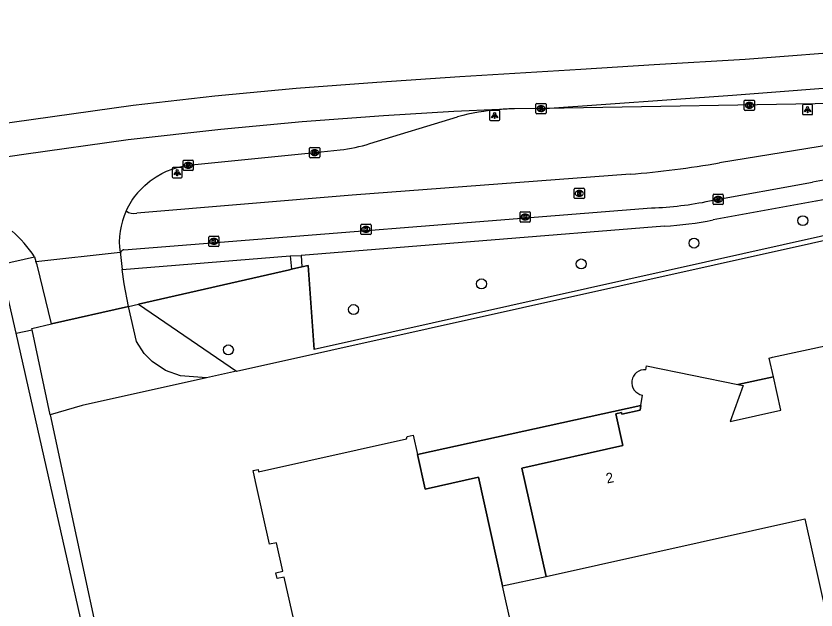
# Model space of a CAD drawing. Extents: x 160806 to 161707, y 383697 to 384148.
# Drawn here: x 161561.9 to 161640.7, y 383938.2 to 383996.6 of the extents above; entities that cross this region are included whole.
import ezdxf

# ---------------------------------------------------------------- set-up
doc = ezdxf.new("R2010")
doc.units = 0
for name, color, linetype in [('IMGEO_Boom', 7, 'Continuous'), ('IMGEO_Fietspad_gesloten', 7, 'Continuous'), ('IMGEO_Groenvoorziening', 7, 'Continuous'), ('IMGEO_Hek', 7, 'Continuous'), ('IMGEO_Kolk', 7, 'Continuous'), ('IMGEO_Lichtpunt', 7, 'Continuous'), ('IMGEO_Pand', 7, 'Continuous'), ('IMGEO_Pand_nummerreeks', 7, 'Continuous'), ('IMGEO_Pand_overbouw', 7, 'Continuous'), ('IMGEO_Rijbaan_lokaal_gesloten', 7, 'Continuous'), ('IMGEO_Rijbaan_lokaal_open', 7, 'Continuous'), ('IMGEO_Rioolput', 7, 'Continuous'), ('IMGEO_Voetpad_open', 7, 'Continuous')]:
    doc.layers.add(name, color=color, linetype=linetype)

msp = doc.modelspace()

# ---------------------------------------------------------------- linework, layer by layer
at = {"layer": 'IMGEO_Boom'}
for centre in [(161639.398, 383976.482), (161628.685, 383974.273), (161617.583, 383972.225), (161607.767, 383970.262), (161595.169, 383967.742), (161582.85, 383963.771)]:
    msp.add_circle(centre, 0.489, dxfattribs=at)
at = {"layer": 'IMGEO_Fietspad_gesloten'}
for points in [[(161652.014, 383985.545), (161631.18, 383982.155)], [(161622.388, 383981.04), (161595.026, 383978.975), (161573.832, 383977.231)], [(161630.223, 383978.423), (161640.346, 383980.265)], [(161572.575, 383973.622), (161624.515, 383977.73)], [(161572.194, 383973.368), (161572.229, 383973.164)]]:
    msp.add_lwpolyline(points, dxfattribs=at)
for centre, radius, start, end in [((161612.123, 384097.202), 116.615, 275.04997, 279.40535), ((161690.597, 383714.53), 270.445, 98.22915, 100.70838), ((161623.202, 384012.399), 34.694, 272.16899, 281.67565), ((161573.512, 383978.353), 1.167, 232.06416, 285.89031), ((161572.621, 383973.228), 0.397, 96.6008, 189.26013)]:
    msp.add_arc(centre, radius, start, end, dxfattribs=at)
at = {"layer": 'IMGEO_Groenvoorziening'}
for points in [[(161661.841, 383973.012), (161660.383, 383979.219), (161591.289, 383963.808), (161590.712, 383972.073), (161590.074, 383971.928)], [(161589.067, 383971.699), (161588.861, 383971.653), (161574, 383968.274)], [(161573.018, 383968.051), (161574, 383968.274)], [(161574, 383968.274), (161583.645, 383961.688)]]:
    msp.add_lwpolyline(points, dxfattribs=at)
at = {"layer": 'IMGEO_Hek'}
for points in [[(161590.074, 383971.928), (161590.712, 383972.073), (161591.289, 383963.808)], [(161574, 383968.274), (161588.861, 383971.653)], [(161588.861, 383971.653), (161589.067, 383971.699)], [(161589.067, 383971.699), (161590.074, 383971.928)], [(161573.018, 383968.051), (161574, 383968.274)], [(161565.428, 383966.326), (161573.018, 383968.051)], [(161563.498, 383965.879), (161565.428, 383966.326)], [(161563.526, 383965.747), (161563.498, 383965.879)], [(161565.319, 383957.39), (161563.526, 383965.747)]]:
    msp.add_lwpolyline(points, dxfattribs=at)
at = {"layer": 'IMGEO_Kolk'}
for p, q in [((161613.127, 383987.079), (161613.127, 383987.931)), ((161613.202, 383988.005), (161614.054, 383988.005)), ((161613.615, 383987.785), (161613.64, 383987.785)), ((161614.128, 383987.931), (161614.128, 383987.079)), ((161633.638, 383987.404), (161633.638, 383988.256)), ((161633.713, 383988.33), (161634.565, 383988.33)), ((161634.126, 383988.11), (161634.151, 383988.11)), ((161634.639, 383988.256), (161634.639, 383987.404)), ((161614.054, 383987.005), (161613.202, 383987.005)), ((161613.638, 383987.225), (161613.613, 383987.225)), ((161634.565, 383987.33), (161633.713, 383987.33)), ((161634.149, 383987.55), (161634.124, 383987.55)), ((161590.847, 383982.749), (161590.847, 383983.601)), ((161590.922, 383983.675), (161591.774, 383983.675)), ((161591.335, 383983.455), (161591.36, 383983.455)), ((161591.848, 383983.601), (161591.848, 383982.749)), ((161578.396, 383981.499), (161578.396, 383982.351)), ((161578.471, 383982.425), (161579.323, 383982.425)), ((161579.397, 383982.351), (161579.397, 383981.499)), ((161591.774, 383982.675), (161590.922, 383982.675)), ((161591.358, 383982.895), (161591.333, 383982.895)), ((161578.907, 383981.645), (161578.882, 383981.645)), ((161578.884, 383982.205), (161578.909, 383982.205)), ((161579.323, 383981.425), (161578.471, 383981.425)), ((161630.56, 383978.15), (161630.56, 383979.002)), ((161630.635, 383979.076), (161631.487, 383979.076)), ((161631.048, 383978.856), (161631.073, 383978.856)), ((161631.561, 383979.002), (161631.561, 383978.15)), ((161631.487, 383978.076), (161630.635, 383978.076)), ((161631.071, 383978.296), (161631.046, 383978.296)), ((161611.562, 383976.422), (161611.562, 383977.274)), ((161611.637, 383977.348), (161612.489, 383977.348)), ((161612.05, 383977.128), (161612.075, 383977.128)), ((161612.563, 383977.274), (161612.563, 383976.422)), ((161595.889, 383975.2), (161595.889, 383976.052)), ((161595.964, 383976.126), (161596.816, 383976.126)), ((161596.89, 383976.052), (161596.89, 383975.2)), ((161612.489, 383976.348), (161611.637, 383976.348)), ((161612.073, 383976.568), (161612.048, 383976.568)), ((161596.4, 383975.346), (161596.375, 383975.346)), ((161596.377, 383975.906), (161596.402, 383975.906)), ((161580.923, 383974.019), (161580.923, 383974.871)), ((161580.998, 383974.945), (161581.85, 383974.945)), ((161581.411, 383974.725), (161581.436, 383974.725)), ((161581.924, 383974.871), (161581.924, 383974.019)), ((161596.816, 383975.126), (161595.964, 383975.126)), ((161581.85, 383973.945), (161580.998, 383973.945)), ((161581.434, 383974.165), (161581.409, 383974.165))]:
    msp.add_line(p, q, dxfattribs=at)
for points in [[(161613.127, 383987.079), (161613.127, 383987.931)], [(161613.202, 383988.005), (161614.054, 383988.005)], [(161614.128, 383987.931), (161614.128, 383987.079)], [(161633.638, 383987.404), (161633.638, 383988.256)], [(161633.713, 383988.33), (161634.565, 383988.33)], [(161633.959, 383988.03), (161634.082, 383988.03), (161634.082, 383987.879), (161634.212, 383988.03), (161634.376, 383988.03), (161634.23, 383987.879), (161634.383, 383987.63), (161634.231, 383987.63), (161634.146, 383987.794), (161634.082, 383987.727), (161634.082, 383987.63), (161633.959, 383987.63), (161633.959, 383988.03)], [(161634.639, 383988.256), (161634.639, 383987.404)], [(161614.054, 383987.005), (161613.202, 383987.005)], [(161613.448, 383987.705), (161613.571, 383987.705), (161613.571, 383987.554), (161613.701, 383987.705), (161613.865, 383987.705), (161613.719, 383987.554), (161613.872, 383987.305), (161613.72, 383987.305), (161613.635, 383987.469), (161613.571, 383987.402), (161613.571, 383987.305), (161613.448, 383987.305), (161613.448, 383987.705)], [(161634.565, 383987.33), (161633.713, 383987.33)], [(161590.847, 383982.749), (161590.847, 383983.601)], [(161590.922, 383983.675), (161591.774, 383983.675)], [(161591.168, 383983.375), (161591.291, 383983.375), (161591.291, 383983.224), (161591.421, 383983.375), (161591.585, 383983.375), (161591.439, 383983.224), (161591.592, 383982.975), (161591.44, 383982.975), (161591.355, 383983.139), (161591.291, 383983.072), (161591.291, 383982.975), (161591.168, 383982.975), (161591.168, 383983.375)], [(161591.848, 383983.601), (161591.848, 383982.749)], [(161578.396, 383981.499), (161578.396, 383982.351)], [(161578.471, 383982.425), (161579.323, 383982.425)], [(161579.397, 383982.351), (161579.397, 383981.499)], [(161591.774, 383982.675), (161590.922, 383982.675)], [(161578.717, 383982.125), (161578.84, 383982.125), (161578.84, 383981.974), (161578.97, 383982.125), (161579.134, 383982.125), (161578.988, 383981.974), (161579.141, 383981.725), (161578.989, 383981.725), (161578.904, 383981.889), (161578.84, 383981.822), (161578.84, 383981.725), (161578.717, 383981.725), (161578.717, 383982.125)], [(161579.323, 383981.425), (161578.471, 383981.425)], [(161630.56, 383978.15), (161630.56, 383979.002)], [(161630.635, 383979.076), (161631.487, 383979.076)], [(161630.881, 383978.776), (161631.004, 383978.776), (161631.004, 383978.625), (161631.134, 383978.776), (161631.298, 383978.776), (161631.152, 383978.625), (161631.305, 383978.376), (161631.153, 383978.376), (161631.068, 383978.54), (161631.004, 383978.473), (161631.004, 383978.376), (161630.881, 383978.376), (161630.881, 383978.776)], [(161631.561, 383979.002), (161631.561, 383978.15)], [(161631.487, 383978.076), (161630.635, 383978.076)], [(161611.562, 383976.422), (161611.562, 383977.274)], [(161611.637, 383977.348), (161612.489, 383977.348)], [(161611.883, 383977.048), (161612.006, 383977.048), (161612.006, 383976.897), (161612.136, 383977.048), (161612.3, 383977.048), (161612.154, 383976.897), (161612.307, 383976.648), (161612.155, 383976.648), (161612.07, 383976.812), (161612.006, 383976.745), (161612.006, 383976.648), (161611.883, 383976.648), (161611.883, 383977.048)], [(161612.563, 383977.274), (161612.563, 383976.422)], [(161595.889, 383975.2), (161595.889, 383976.052)], [(161595.964, 383976.126), (161596.816, 383976.126)], [(161596.89, 383976.052), (161596.89, 383975.2)], [(161612.489, 383976.348), (161611.637, 383976.348)], [(161596.21, 383975.826), (161596.333, 383975.826), (161596.333, 383975.675), (161596.463, 383975.826), (161596.627, 383975.826), (161596.481, 383975.675), (161596.634, 383975.426), (161596.482, 383975.426), (161596.397, 383975.59), (161596.333, 383975.523), (161596.333, 383975.426), (161596.21, 383975.426), (161596.21, 383975.826)], [(161580.923, 383974.019), (161580.923, 383974.871)], [(161580.998, 383974.945), (161581.85, 383974.945)], [(161581.244, 383974.645), (161581.367, 383974.645), (161581.367, 383974.494), (161581.497, 383974.645), (161581.661, 383974.645), (161581.515, 383974.494), (161581.668, 383974.245), (161581.516, 383974.245), (161581.431, 383974.409), (161581.367, 383974.342), (161581.367, 383974.245), (161581.244, 383974.245), (161581.244, 383974.645)], [(161581.924, 383974.871), (161581.924, 383974.019)], [(161596.816, 383975.126), (161595.964, 383975.126)], [(161581.85, 383973.945), (161580.998, 383973.945)]]:
    msp.add_lwpolyline(points, dxfattribs=at)
for centre, start, end in [((161613.204, 383987.929), 91.55205, 178.44795), ((161613.204, 383987.929), 91.55205, 178.44795), ((161614.052, 383987.929), 1.55205, 88.44795), ((161614.052, 383987.929), 1.55205, 88.44795), ((161633.715, 383988.254), 91.55205, 178.44795), ((161633.715, 383988.254), 91.55205, 178.44795), ((161634.563, 383988.254), 1.55205, 88.44795), ((161634.563, 383988.254), 1.55205, 88.44795), ((161613.204, 383987.081), 181.55205, 268.44795), ((161613.204, 383987.081), 181.55205, 268.44795), ((161614.052, 383987.081), 271.55205, 358.44795), ((161614.052, 383987.081), 271.55205, 358.44795), ((161633.715, 383987.406), 181.55205, 268.44795), ((161633.715, 383987.406), 181.55205, 268.44795), ((161634.563, 383987.406), 271.55205, 358.44795), ((161634.563, 383987.406), 271.55205, 358.44795), ((161590.924, 383983.599), 91.55205, 178.44795), ((161590.924, 383983.599), 91.55205, 178.44795), ((161591.772, 383983.599), 1.55205, 88.44795), ((161591.772, 383983.599), 1.55205, 88.44795), ((161578.473, 383982.349), 91.55205, 178.44795), ((161578.473, 383982.349), 91.55205, 178.44795), ((161579.321, 383982.349), 1.55205, 88.44795), ((161579.321, 383982.349), 1.55205, 88.44795), ((161590.924, 383982.751), 181.55205, 268.44795), ((161590.924, 383982.751), 181.55205, 268.44795), ((161591.772, 383982.751), 271.55205, 358.44795), ((161591.772, 383982.751), 271.55205, 358.44795), ((161578.473, 383981.501), 181.55205, 268.44795), ((161578.473, 383981.501), 181.55205, 268.44795), ((161579.321, 383981.501), 271.55205, 358.44795), ((161579.321, 383981.501), 271.55205, 358.44795), ((161630.637, 383979), 91.55205, 178.44795), ((161630.637, 383979), 91.55205, 178.44795), ((161631.485, 383979), 1.55205, 88.44795), ((161631.485, 383979), 1.55205, 88.44795), ((161630.637, 383978.152), 181.55205, 268.44795), ((161630.637, 383978.152), 181.55205, 268.44795), ((161631.485, 383978.152), 271.55205, 358.44795), ((161631.485, 383978.152), 271.55205, 358.44795), ((161611.639, 383977.272), 91.55205, 178.44795), ((161611.639, 383977.272), 91.55205, 178.44795), ((161612.487, 383977.272), 1.55205, 88.44795), ((161612.487, 383977.272), 1.55205, 88.44795), ((161595.966, 383976.05), 91.55205, 178.44795), ((161595.966, 383976.05), 91.55205, 178.44795), ((161596.814, 383976.05), 1.55205, 88.44795), ((161596.814, 383976.05), 1.55205, 88.44795), ((161611.639, 383976.424), 181.55205, 268.44795), ((161611.639, 383976.424), 181.55205, 268.44795), ((161612.487, 383976.424), 271.55205, 358.44795), ((161612.487, 383976.424), 271.55205, 358.44795), ((161595.966, 383975.202), 181.55205, 268.44795), ((161595.966, 383975.202), 181.55205, 268.44795), ((161596.814, 383975.202), 271.55205, 358.44795), ((161596.814, 383975.202), 271.55205, 358.44795), ((161581, 383974.869), 91.55205, 178.44795), ((161581, 383974.869), 91.55205, 178.44795), ((161581.848, 383974.869), 1.55205, 88.44795), ((161581.848, 383974.869), 1.55205, 88.44795), ((161581, 383974.021), 181.55205, 268.44795), ((161581, 383974.021), 181.55205, 268.44795), ((161581.848, 383974.021), 271.55205, 358.44795), ((161581.848, 383974.021), 271.55205, 358.44795)]:
    msp.add_arc(centre, 0.0765, start, end, dxfattribs=at)
for centre, major_axis, ratio, start_param, end_param in [((161613.614, 383987.505), (-0.387, 0.002), 0.722429, 4.712389, 7.853982), ((161613.639, 383987.505), (-0.39, 0.002), 0.717154, 1.570796, 4.712389), ((161634.125, 383987.83), (-0.387, 0.002), 0.722429, 4.712389, 7.853982), ((161634.15, 383987.83), (-0.39, 0.002), 0.717154, 1.570796, 4.712389), ((161591.334, 383983.175), (-0.387, 0.002), 0.722429, 4.712389, 7.853982), ((161591.359, 383983.175), (-0.39, 0.002), 0.717154, 1.570796, 4.712389), ((161578.883, 383981.925), (-0.387, 0.002), 0.722429, 4.712389, 7.853982), ((161578.908, 383981.925), (-0.39, 0.002), 0.717154, 1.570796, 4.712389), ((161631.047, 383978.576), (-0.387, 0.002), 0.722429, 4.712389, 7.853982), ((161631.072, 383978.576), (-0.39, 0.002), 0.717154, 1.570796, 4.712389), ((161612.049, 383976.848), (-0.387, 0.002), 0.722429, 4.712389, 7.853982), ((161612.074, 383976.848), (-0.39, 0.002), 0.717154, 1.570796, 4.712389), ((161596.376, 383975.626), (-0.387, 0.002), 0.722429, 4.712389, 7.853982), ((161596.401, 383975.626), (-0.39, 0.002), 0.717154, 1.570796, 4.712389), ((161581.41, 383974.445), (-0.387, 0.002), 0.722429, 4.712389, 7.853982), ((161581.435, 383974.445), (-0.39, 0.002), 0.717154, 1.570796, 4.712389)]:
    msp.add_ellipse(centre, major_axis=major_axis, ratio=ratio, start_param=start_param, end_param=end_param, dxfattribs=at)
at = {"layer": 'IMGEO_Lichtpunt'}
for p, q in [((161639.364, 383987.81), (161639.364, 383987.003)), ((161639.364, 383987.81), (161639.364, 383987.003)), ((161640.266, 383987.905), (161639.458, 383987.905)), ((161640.266, 383987.905), (161639.458, 383987.905)), ((161640.36, 383987.003), (161640.36, 383987.81)), ((161640.36, 383987.003), (161640.36, 383987.81)), ((161608.562, 383987.235), (161608.562, 383986.428)), ((161608.562, 383987.235), (161608.562, 383986.428)), ((161609.464, 383987.33), (161608.656, 383987.33)), ((161609.464, 383987.33), (161608.656, 383987.33)), ((161609.558, 383986.428), (161609.558, 383987.235)), ((161609.558, 383986.428), (161609.558, 383987.235)), ((161608.656, 383986.334), (161609.464, 383986.334)), ((161608.656, 383986.334), (161609.464, 383986.334)), ((161639.458, 383986.909), (161640.266, 383986.909)), ((161639.458, 383986.909), (161640.266, 383986.909)), ((161577.316, 383981.611), (161577.316, 383980.804)), ((161577.316, 383981.611), (161577.316, 383980.804)), ((161578.218, 383981.706), (161577.41, 383981.706)), ((161578.218, 383981.706), (161577.41, 383981.706)), ((161578.312, 383980.804), (161578.312, 383981.611)), ((161578.312, 383980.804), (161578.312, 383981.611)), ((161577.41, 383980.71), (161578.218, 383980.71)), ((161577.41, 383980.71), (161578.218, 383980.71))]:
    msp.add_line(p, q, dxfattribs=at)
for points in [[(161639.738, 383987.474), (161639.777, 383987.446), (161639.589, 383987.184), (161639.551, 383987.211), (161639.738, 383987.474)], [(161639.84, 383987.426), (161639.887, 383987.426), (161639.887, 383987.104), (161639.84, 383987.104), (161639.84, 383987.426)], [(161639.95, 383987.446), (161639.988, 383987.473), (161640.175, 383987.211), (161640.136, 383987.183), (161639.95, 383987.446)], [(161608.936, 383986.899), (161608.975, 383986.871), (161608.787, 383986.609), (161608.749, 383986.636), (161608.936, 383986.899)], [(161609.038, 383986.851), (161609.085, 383986.851), (161609.085, 383986.529), (161609.038, 383986.529), (161609.038, 383986.851)], [(161609.148, 383986.871), (161609.186, 383986.898), (161609.373, 383986.636), (161609.334, 383986.608), (161609.148, 383986.871)], [(161577.69, 383981.275), (161577.729, 383981.247), (161577.541, 383980.985), (161577.503, 383981.012), (161577.69, 383981.275)], [(161577.792, 383981.227), (161577.839, 383981.227), (161577.839, 383980.905), (161577.792, 383980.905), (161577.792, 383981.227)], [(161577.902, 383981.247), (161577.94, 383981.274), (161578.127, 383981.012), (161578.088, 383980.984), (161577.902, 383981.247)]]:
    msp.add_lwpolyline(points, dxfattribs=at)
for centre in [(161609.061, 383987.033), (161639.863, 383987.608), (161577.815, 383981.409)]:
    msp.add_circle(centre, 0.0994, dxfattribs=at)
for centre, start, end in [((161639.458, 383987.81), 90, 180), ((161639.458, 383987.81), 90, 180), ((161640.266, 383987.81), 0, 90), ((161640.266, 383987.81), 0, 90), ((161608.656, 383987.235), 90, 180), ((161608.656, 383987.235), 90, 180), ((161609.464, 383987.235), 0, 90), ((161609.464, 383987.235), 0, 90), ((161639.458, 383987.003), 180, 270), ((161639.458, 383987.003), 180, 270), ((161640.266, 383987.003), 270, 0), ((161640.266, 383987.003), 270, 360), ((161608.656, 383986.428), 180, 270), ((161608.656, 383986.428), 180, 270), ((161609.464, 383986.428), 270, 0), ((161609.464, 383986.428), 270, 360), ((161577.41, 383981.611), 90, 180), ((161577.41, 383981.611), 90, 180), ((161578.218, 383981.611), 0, 90), ((161578.218, 383981.611), 0, 90), ((161577.41, 383980.804), 180, 270), ((161577.41, 383980.804), 180, 270), ((161578.218, 383980.804), 270, 0), ((161578.218, 383980.804), 270, 360)]:
    msp.add_arc(centre, 0.0946, start, end, dxfattribs=at)
at = {"layer": 'IMGEO_Pand'}
for points in [[(161636.5, 383961.134), (161636.09, 383962.971), (161636.41, 383963.042), (161651.22, 383966.246), (161651.275, 383966.421), (161651.781, 383966.534), (161668.642, 383890.98), (161623.195, 383880.838), (161623.29, 383880.412), (161614.09, 383878.359)], [(161623.949, 383961.808), (161624.02, 383962.196), (161632.991, 383960.369)], [(161632.991, 383960.369), (161633.539, 383960.257), (161632.259, 383956.73), (161637.235, 383957.841), (161636.5, 383961.134)], [(161623.44, 383958.286), (161623.6, 383959.326)], [(161623.44, 383958.286), (161623.373, 383957.849), (161621.576, 383957.444), (161621.542, 383957.601), (161621.004, 383957.486), (161621.668, 383954.367), (161611.745, 383952.152), (161614.126, 383941.485), (161639.592, 383947.168), (161644.472, 383925.298), (161619.068, 383919.629), (161620.336, 383913.947), (161637.993, 383917.886), (161641.714, 383901.083), (161643.242, 383894.237), (161628.445, 383890.854), (161625.243, 383890.144), (161623.702, 383897.085), (161619.744, 383896.206), (161609.842, 383940.58), (161607.463, 383951.24), (161602.237, 383950.074), (161601.474, 383953.495)], [(161589.975, 383931.403), (161590.578, 383931.537), (161589.611, 383935.875), (161588.905, 383935.717), (161588.764, 383936.35), (161589.446, 383936.502), (161588.347, 383941.428), (161587.638, 383941.27), (161587.509, 383941.849), (161588.217, 383942.008), (161587.593, 383944.803), (161586.894, 383944.647), (161585.578, 383950.541), (161585.41, 383951.295), (161585.276, 383951.894), (161585.775, 383952.006), (161585.828, 383951.766), (161600.383, 383955.015), (161600.463, 383955.268), (161601.049, 383955.399), (161601.474, 383953.495)]]:
    msp.add_lwpolyline(points, dxfattribs=at)
msp.add_arc((161623.806, 383960.563), 1.254, 83.46938, 260.52258, dxfattribs=at)
at = {"layer": 'IMGEO_Pand_overbouw'}
for points in [[(161636.5, 383961.134), (161632.991, 383960.369), (161633.539, 383960.257), (161632.259, 383956.73), (161637.235, 383957.841)], [(161621.668, 383954.367), (161621.004, 383957.486), (161621.542, 383957.601), (161621.576, 383957.444), (161623.373, 383957.849), (161623.44, 383958.286), (161601.474, 383953.495), (161602.237, 383950.074), (161607.463, 383951.24), (161609.842, 383940.58), (161614.126, 383941.485), (161611.745, 383952.152)]]:
    msp.add_lwpolyline(points, close=True, dxfattribs=at)
at = {"layer": 'IMGEO_Rijbaan_lokaal_gesloten'}
for points in [[(161543.895, 383983.402), (161553.591, 383985.048), (161573.495, 383987.841), (161581.516, 383988.752), (161589.522, 383989.509), (161597.462, 383990.091), (161605.635, 383990.651), (161617.53, 383991.391), (161624.775, 383991.843), (161633.722, 383992.378), (161645.647, 383993.275), (161657.351, 383994.439), (161669.645, 383995.823), (161676.771, 383996.611)], [(161614.008, 383987.53), (161632.485, 383988.83), (161645.674, 383989.845), (161657.249, 383990.978), (161669.205, 383992.339), (161677.19, 383993.249)], [(161677.53, 383990.518), (161674.805, 383990.17), (161662.914, 383988.857), (161654.688, 383988.327), (161650.451, 383988.1), (161644.412, 383988.028), (161614.008, 383987.53)], [(161609.55, 383987.409), (161605.034, 383987.21), (161598.112, 383986.804), (161590.116, 383986.195), (161582.115, 383985.453), (161572.974, 383984.425), (161562.702, 383982.989), (161558.682, 383982.396), (161552.732, 383981.479), (161544.527, 383980.089)], [(161614.008, 383987.53), (161611.005, 383987.481)], [(161596.778, 383984.065), (161605.415, 383986.699)], [(161573.917, 383979.218), (161574.152, 383979.466), (161574.633, 383979.945), (161575.16, 383980.386), (161575.733, 383980.786), (161576.311, 383981.119), (161576.765, 383981.337), (161577.308, 383981.553), (161577.901, 383981.737), (161578.415, 383981.857), (161578.715, 383981.91), (161578.898, 383981.927), (161591.348, 383983.176), (161593.839, 383983.44)], [(161560.426, 383972.163), (161563.758, 383972.924)], [(161563.758, 383972.924), (161563.911, 383972.468)], [(161563.911, 383972.468), (161572.194, 383973.368)], [(161561.955, 383965.404), (161560.426, 383972.163)], [(161586.966, 383854.859), (161586.942, 383854.966), (161586.702, 383856.038), (161585.178, 383862.774), (161563.858, 383956.995), (161561.955, 383965.404)]]:
    msp.add_lwpolyline(points, dxfattribs=at)
for centre, radius, start, end in [((161611.424, 383964.1), 23.385, 94.59621, 104.88971), ((161611.468, 383963.389), 24.097, 91.10076, 94.56512), ((161592.191, 383998.411), 15.061, 276.28083, 287.73022), ((161578.363, 383975.179), 6.007, 137.73997, 157.95544), ((161579.036, 383974.433), 6.924, 154.32942, 188.85036), ((161553.621, 383966.363), 12.075, 32.91368, 48.89961)]:
    msp.add_arc(centre, radius, start, end, dxfattribs=at)
at = {"layer": 'IMGEO_Rijbaan_lokaal_open'}
for points in [[(161583.645, 383961.688), (161649.545, 383976.321)], [(161580.704, 383961.035), (161568.451, 383958.314), (161565.319, 383957.39)], [(161583.645, 383961.688), (161580.704, 383961.035)], [(161632.991, 383960.369), (161636.5, 383961.134)], [(161601.474, 383953.495), (161623.44, 383958.286)], [(161565.319, 383957.39), (161570.493, 383933.267), (161571.202, 383933.39)]]:
    msp.add_lwpolyline(points, dxfattribs=at)
at = {"layer": 'IMGEO_Rioolput'}
for p, q in [((161616.89, 383978.739), (161616.89, 383979.591)), ((161616.965, 383979.665), (161617.817, 383979.665)), ((161617.378, 383979.445), (161617.403, 383979.445)), ((161617.891, 383979.591), (161617.891, 383978.739)), ((161617.817, 383978.665), (161616.965, 383978.665)), ((161617.401, 383978.885), (161617.376, 383978.885))]:
    msp.add_line(p, q, dxfattribs=at)
for points in [[(161616.89, 383978.739), (161616.89, 383979.591)], [(161616.965, 383979.665), (161617.817, 383979.665)], [(161617.479, 383979.363), (161617.227, 383979.365), (161617.227, 383978.965)], [(161617.227, 383978.965), (161617.351, 383978.965), (161617.351, 383979.127), (161617.362, 383979.127)], [(161617.405, 383979.284), (161617.351, 383979.284), (161617.351, 383979.203)], [(161617.351, 383979.203), (161617.403, 383979.203)], [(161617.891, 383979.591), (161617.891, 383978.739)], [(161617.817, 383978.665), (161616.965, 383978.665)], [(161617.409, 383979.098), (161617.48, 383978.965), (161617.62, 383978.965), (161617.555, 383979.091)]]:
    msp.add_lwpolyline(points, dxfattribs=at)
for centre, radius, start, end in [((161616.967, 383979.589), 0.0765, 91.55205, 178.44795), ((161616.967, 383979.589), 0.0765, 91.55205, 178.44795), ((161617.361, 383979.074), 0.0533, 26.02933, 88.69889), ((161617.387, 383979.392), 0.19, 274.7715, 282.96867), ((161617.411, 383979.188), 0.0964, 77.00612, 93.18647), ((161617.425, 383979.245), 0.0378, 276.66336, 79.67722), ((161617.478, 383979.253), 0.109, 350.36119, 89.41601), ((161617.476, 383979.253), 0.112, 277.58423, 350.98172), ((161617.46, 383979.038), 0.108, 29.51342, 73.79051), ((161617.815, 383979.589), 0.0765, 1.55205, 88.44795), ((161617.815, 383979.589), 0.0765, 1.55205, 88.44795), ((161616.967, 383978.741), 0.0765, 181.55205, 268.44795), ((161616.967, 383978.741), 0.0765, 181.55205, 268.44795), ((161617.815, 383978.741), 0.0765, 271.55205, 358.44795), ((161617.815, 383978.741), 0.0765, 271.55205, 358.44795)]:
    msp.add_arc(centre, radius, start, end, dxfattribs=at)
for centre, major_axis, ratio, start_param, end_param in [((161617.377, 383979.165), (-0.387, 0.002), 0.722429, 4.712389, 7.853982), ((161617.402, 383979.165), (-0.39, 0.002), 0.717154, 1.570796, 4.712389)]:
    msp.add_ellipse(centre, major_axis=major_axis, ratio=ratio, start_param=start_param, end_param=end_param, dxfattribs=at)
at = {"layer": 'IMGEO_Voetpad_open'}
for points in [[(161640.693, 383978.402), (161630.578, 383976.553)], [(161625.778, 383975.932), (161590, 383973.07)], [(161572.229, 383973.164), (161572.407, 383971.679)], [(161572.407, 383971.679), (161588.932, 383973.007)], [(161588.932, 383973.007), (161590, 383973.07)], [(161588.932, 383973.007), (161589.067, 383971.699)], [(161590, 383973.07), (161590.074, 383971.928)], [(161565.428, 383966.326), (161564.023, 383972.131), (161563.911, 383972.468)], [(161573.018, 383968.051), (161572.609, 383970.265), (161572.407, 383971.679)], [(161590.074, 383971.928), (161589.067, 383971.699)], [(161573.018, 383968.051), (161565.428, 383966.326)], [(161580.704, 383961.035), (161578.129, 383961.225), (161576.648, 383961.751), (161575.338, 383962.621), (161574.556, 383963.419), (161573.792, 383964.594), (161573.018, 383968.051)], [(161561.955, 383965.404), (161563.526, 383965.747)], [(161563.526, 383965.747), (161563.498, 383965.879), (161565.428, 383966.326)], [(161565.319, 383957.39), (161563.526, 383965.747)]]:
    msp.add_lwpolyline(points, dxfattribs=at)
for centre, radius, start, end in [((161697.464, 383676.332), 307.358, 98.47142, 100.64397), ((161623.313, 384013.845), 37.993, 273.7197, 281.02369)]:
    msp.add_arc(centre, radius, start, end, dxfattribs=at)

# ---------------------------------------------------------------- texts
at = {"layer": 'IMGEO_Pand_nummerreeks'}
msp.add_text('2', height=1, rotation=12.16962, dxfattribs=at).set_placement((161620.129, 383950.619))

doc.saveas('drawing.dxf')
